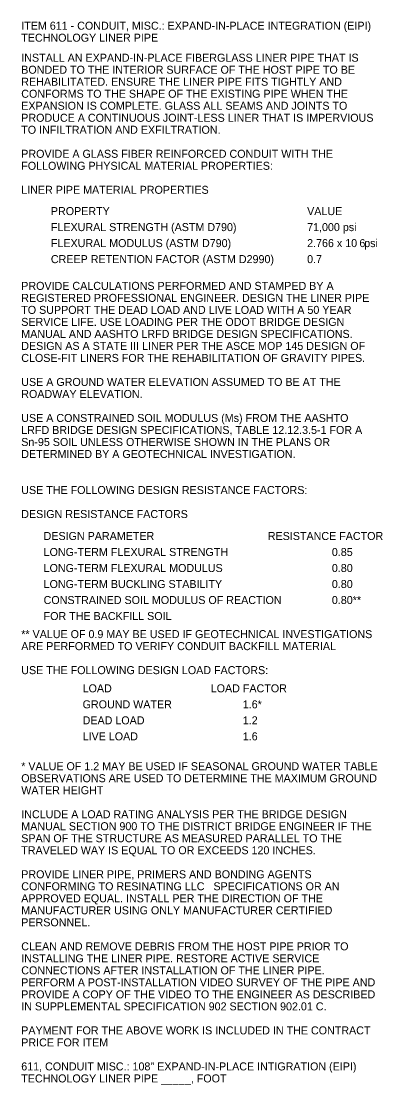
# Model space of a CAD drawing. Extents: x 0 to 34, y 0 to 41.9.
# Drawn here: x 17.24 to 23.56, y 23.29 to 41.89 of the extents above; entities that cross this region are included whole.
import ezdxf

# ---------------------------------------------------------------- set-up
doc = ezdxf.new("R2010")
doc.units = 0
doc.layers.add('Default', color=7, linetype='Continuous')
doc.layers.add('SH_Text', color=7, linetype='Continuous')

msp = doc.modelspace()

# ---------------------------------------------------------------- texts
at = {"layer": 'Default'}
for s, p in [('PROPERTY', (17.758, 38.503)), ('VALUE', (22.238, 38.503)), ('FLEXURAL STRENGTH (ASTM D790)', (17.758, 38.223)), ('71,000 psi', (22.238, 38.223)), ('FLEXURAL MODULUS (ASTM D790)', (17.758, 37.943)), ('2.766 x 10', (22.238, 37.943)), ('6', (23.152, 37.943)), (' psi', (23.184, 37.943)), ('CREEP RETENTION FACTOR (ASTM D2990)', (17.758, 37.663)), ('0.7', (22.238, 37.663)), ('DESIGN PARAMETER', (17.631, 32.821)), ('RESISTANCE FACTOR', (21.551, 32.821)), ('LONG-TERM FLEXURAL STRENGTH', (17.631, 32.541)), ('0.85', (22.671, 32.541)), ('LONG-TERM FLEXURAL MODULUS', (17.631, 32.261)), ('0.80', (22.671, 32.261)), ('LONG-TERM BUCKLING STABILITY', (17.631, 31.981)), ('0.80', (22.671, 31.981)), ('CONSTRAINED SOIL MODULUS OF REACTION', (17.631, 31.701)), ('0.80**', (22.671, 31.701)), ('FOR THE BACKFILL SOIL', (17.631, 31.421)), ('LOAD', (18.313, 30.157)), ('LOAD FACTOR', (20.553, 30.157)), ('GROUND WATER', (18.313, 29.877)), ('1.6*', (21.113, 29.877)), ('DEAD LOAD', (18.313, 29.597)), ('1.2', (21.113, 29.597)), ('LIVE LOAD', (18.313, 29.317)), ('1.6', (21.113, 29.317))]:
    msp.add_text(s, height=0.14, dxfattribs=at).set_placement(p)
at = {"layer": 'SH_Text'}
for s, p in [('ITEM 611 - CONDUIT, MISC.: EXPAND-IN-PLACE INTEGRATION (EIPI) ', (17.24, 41.745)), ('TECHNOLOGY LINER PIPE', (17.24, 41.535)), ('INSTALL AN EXPAND-IN-PLACE FIBERGLASS LINER PIPE THAT IS ', (17.24, 41.185)), ('BONDED TO THE INTERIOR SURFACE OF THE HOST PIPE TO BE ', (17.24, 40.975)), ('REHABILITATED. ENSURE THE LINER PIPE FITS TIGHTLY AND ', (17.24, 40.765)), ('CONFORMS TO THE SHAPE OF THE EXISTING PIPE WHEN THE ', (17.24, 40.555)), ('EXPANSION IS COMPLETE. GLASS ALL SEAMS AND JOINTS TO ', (17.24, 40.345)), ('PRODUCE A CONTINUOUS JOINT-LESS LINER THAT IS IMPERVIOUS ', (17.24, 40.135)), ('TO INFILTRATION AND EXFILTRATION.', (17.24, 39.925)), ('PROVIDE A GLASS FIBER REINFORCED CONDUIT WITH THE ', (17.24, 39.505)), ('FOLLOWING PHYSICAL MATERIAL PROPERTIES:', (17.24, 39.295)), ('LINER PIPE MATERIAL PROPERTIES', (17.24, 38.875)), ('PROVIDE CALCULATIONS PERFORMED AND STAMPED BY A ', (17.24, 37.195)), ('REGISTERED PROFESSIONAL ENGINEER. DESIGN THE LINER PIPE ', (17.24, 36.985)), ('TO SUPPORT THE DEAD LOAD AND LIVE LOAD WITH A 50 YEAR ', (17.24, 36.775)), ('SERVICE LIFE. USE LOADING PER THE ODOT BRIDGE DESIGN ', (17.24, 36.565)), ('MANUAL AND AASHTO LRFD BRIDGE DESIGN SPECIFICATIONS.  ', (17.24, 36.355)), ('DESIGN AS A STATE III LINER PER THE ASCE MOP 145 DESIGN OF ', (17.24, 36.145)), ('CLOSE-FIT LINERS FOR THE REHABILITATION OF GRAVITY PIPES. ', (17.24, 35.935)), ('USE A GROUND WATER ELEVATION ASSUMED TO BE AT THE ', (17.24, 35.515)), ('ROADWAY ELEVATION.', (17.24, 35.305)), ('USE A CONSTRAINED SOIL MODULUS (Ms) FROM THE AASHTO ', (17.24, 34.885)), ('LRFD BRIDGE DESIGN SPECIFICATIONS, TABLE 12.12.3.5-1 FOR A ', (17.24, 34.675)), ('Sn-95 SOIL UNLESS OTHERWISE SHOWN IN THE PLANS OR ', (17.24, 34.465)), ('DETERMINED BY A GEOTECHNICAL INVESTIGATION. ', (17.24, 34.255)), ('USE THE FOLLOWING DESIGN RESISTANCE FACTORS:', (17.24, 33.625)), ('DESIGN RESISTANCE FACTORS', (17.24, 33.205)), ('** VALUE OF 0.9 MAY BE USED IF GEOTECHNICAL INVESTIGATIONS ', (17.24, 31.105)), ('ARE PERFORMED TO VERIFY CONDUIT BACKFILL MATERIAL', (17.24, 30.895)), ('USE THE FOLLOWING DESIGN LOAD FACTORS:', (17.24, 30.475)), ('* VALUE OF 1.2 MAY BE USED IF SEASONAL GROUND WATER TABLE ', (17.24, 28.795)), ('OBSERVATIONS ARE USED TO DETERMINE THE MAXIMUM GROUND ', (17.24, 28.585)), ('WATER HEIGHT   ', (17.24, 28.375)), ('INCLUDE A LOAD RATING ANALYSIS PER THE BRIDGE DESIGN ', (17.24, 27.955)), ('MANUAL SECTION 900 TO THE DISTRICT BRIDGE ENGINEER IF THE ', (17.24, 27.745)), ('SPAN OF THE STRUCTURE AS MEASURED PARALLEL TO THE ', (17.24, 27.535)), ('TRAVELED WAY IS EQUAL TO OR EXCEEDS 120 INCHES. ', (17.24, 27.325)), ('PROVIDE LINER PIPE, PRIMERS AND BONDING AGENTS ', (17.24, 26.905)), ('CONFORMING TO RESINATING LLC   SPECIFICATIONS OR AN ', (17.24, 26.695)), ('APPROVED EQUAL. INSTALL PER THE DIRECTION OF THE ', (17.24, 26.485)), ('MANUFACTURER USING ONLY MANUFACTURER CERTIFIED ', (17.24, 26.275)), ('PERSONNEL.', (17.24, 26.065)), ('CLEAN AND REMOVE DEBRIS FROM THE HOST PIPE PRIOR TO ', (17.24, 25.645)), ('INSTALLING THE LINER PIPE. RESTORE ACTIVE SERVICE ', (17.24, 25.435)), ('CONNECTIONS AFTER INSTALLATION OF THE LINER PIPE. ', (17.24, 25.225)), ('PERFORM A POST-INSTALLATION VIDEO SURVEY OF THE PIPE AND ', (17.24, 25.015)), ('PROVIDE A COPY OF THE VIDEO TO THE ENGINEER AS DESCRIBED ', (17.24, 24.805)), ('IN SUPPLEMENTAL SPECIFICATION 902 SECTION 902.01 C. ', (17.24, 24.595)), ('PAYMENT FOR THE ABOVE WORK IS INCLUDED IN THE CONTRACT ', (17.24, 24.175)), ('PRICE FOR ITEM', (17.24, 23.965)), ('611, CONDUIT MISC.: 108" EXPAND-IN-PLACE INTIGRATION (EIPI) ', (17.24, 23.545)), ('TECHNOLOGY LINER PIPE _____, FOOT', (17.24, 23.335))]:
    msp.add_text(s, height=0.14, dxfattribs=at).set_placement(p)

doc.saveas('drawing.dxf')
